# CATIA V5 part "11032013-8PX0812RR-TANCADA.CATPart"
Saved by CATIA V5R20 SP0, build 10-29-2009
Part number: 11032013-8PX0812RR-TANCADA
Revision: ANY
Definition: UNKNOWN
Nomenclature: 11032013-8PX0812RR-TANCADA
Source: Unknown
Bounding box of the stored display mesh (mm): x 0 to 155, y -11.2 to 0, z -12.2 to 0
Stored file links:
  C:\Users\Utente\Desktop\IO LAVORO\3D X SITO CF\CUMSA\3D files CX.013058\CX 013058\11032013-8PX0812RR-TANCADA.CATPart
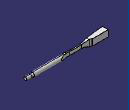
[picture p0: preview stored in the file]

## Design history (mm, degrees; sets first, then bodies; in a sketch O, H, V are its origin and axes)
Body1 "Redondeo6" (main body)
  Solid1: solid without history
